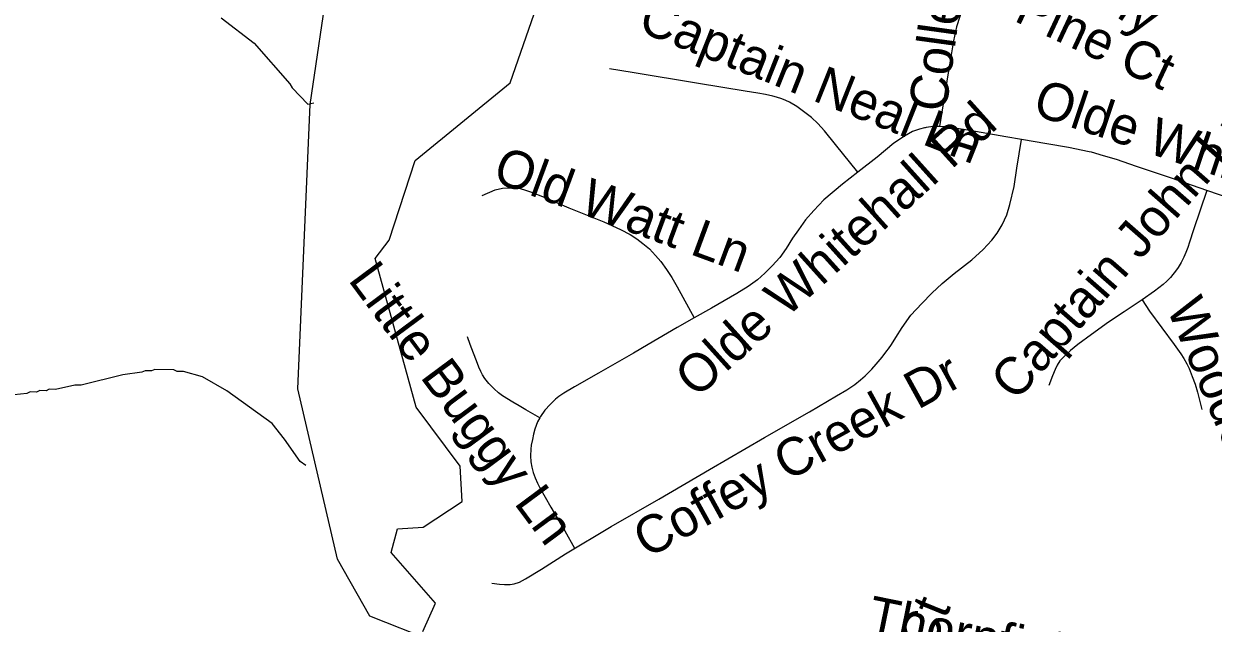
# Model space of a CAD drawing. Extents: x 1383679 to 1536984, y 460658 to 651027.
# Drawn here: x 1421601 to 1424590, y 516365 to 517873 of the extents above; entities that cross this region are included whole.
import ezdxf

# ---------------------------------------------------------------- set-up
doc = ezdxf.new("R2010")
doc.units = 0
for name, color, linetype in [('Default', 7, 'Continuous'), ('Exist Boundary Political City Limit New', 7, 'Continuous'), ('Exist Hydrographic Creek Single Shore', 7, 'Continuous'), ('Exist Hydrographic Misc Water Feature', 7, 'Continuous'), ('Exist Road Non-System Type 51', 7, 'Continuous'), ('Exist Road Non-System Type 51 Label', 7, 'Continuous'), ('Map Preparation Boundary City Limit Buffer Line', 7, 'Continuous')]:
    doc.layers.add(name, color=color, linetype=linetype)

msp = doc.modelspace()

# ---------------------------------------------------------------- linework, layer by layer
at = {"layer": 'Default'}
msp.add_lwpolyline([(1422603.5, 516344.2), (1422635.4, 516415.8), (1422524.4, 516543), (1422540.4, 516602.5), (1422604.6, 516606.3), (1422702.4, 516671.3), (1422697.2, 516759.8), (1422587.1, 516908.5), (1422484, 517282.3), (1422519.2, 517328.5), (1422584.4, 517528.7), (1422823.6, 517723.8), (1422904, 517956.5)], dxfattribs=at)
at = {"layer": 'Exist Boundary Political City Limit New'}
msp.add_lwpolyline([(1422603.5, 516344.2), (1422635.4, 516415.8), (1422524.4, 516543), (1422540.4, 516602.5), (1422604.6, 516606.3), (1422702.4, 516671.3), (1422697.2, 516759.8), (1422587.1, 516908.5), (1422484, 517282.3), (1422519.2, 517328.5), (1422584.4, 517528.7), (1422823.6, 517723.8), (1422904, 517956.5)], dxfattribs=at)
at = {"layer": 'Exist Hydrographic Creek Single Shore'}
msp.add_lwpolyline([(1424072.3, 513492.8), (1423994, 513542), (1423828.5, 513762.7), (1423689.5, 514339.8), (1423609.5, 514541.7), (1423406.5, 514821.5), (1423185.5, 515036), (1423056.5, 515229), (1423060.5, 515461.9), (1423124.5, 515746.2), (1423093.5, 515845.3), (1422831.5, 516093.5), (1422627.5, 516320.8), (1422470.6, 516383.1), (1422389.5, 516525.8), (1422289.5, 516954.5), (1422320.6, 517669.5), (1422416.5, 518317.5), (1422566.9, 518673)], dxfattribs=at)
at = {"layer": 'Exist Hydrographic Misc Water Feature'}
for points in [[(1422097.3, 517887.3), (1422179.9, 517823.5), (1422269.8, 517721.5), (1422275.6, 517711.5), (1422314.7, 517670.5), (1422329.7, 517674.1)], [(1422309.4, 516761.3), (1422295.2, 516771.4), (1422256.4, 516828.2), (1422225.3, 516866.9), (1422111, 516949.5), (1422049.7, 516984.8), (1422002.1, 516997.9), (1421986.1, 516998.2), (1421978.2, 517002.4), (1421930.2, 517003.5), (1421922.1, 516999.7), (1421906.1, 517000), (1421898, 516996.2), (1421849.8, 516989.3), (1421745.2, 516963.7), (1421729.2, 516964), (1421681, 516953.1), (1421665.1, 516953.5), (1421657, 516949.7), (1421641, 516950), (1421632.9, 516946.2), (1421616.9, 516946.6), (1421608.8, 516942.8), (1421576.7, 516939.5)]]:
    msp.add_lwpolyline(points, dxfattribs=at)
at = {"layer": 'Exist Road Non-System Type 51'}
for points in [[(1423965.7, 517924.5), (1423953.1, 517891.2), (1423944.4, 517865.2), (1423936.9, 517830), (1423925.6, 517759.1), (1423902.4, 517613.9)], [(1423696.5, 517499), (1423640.6, 517569.3), (1423613.4, 517602.9), (1423596.1, 517621.5), (1423580.2, 517636.5), (1423564, 517649.8), (1423543.6, 517664.1), (1423525, 517675.1), (1423515.5, 517679.8), (1423506.2, 517683.4), (1423492.6, 517687.7), (1423483.3, 517690.3), (1423464.4, 517694.4), (1423445.5, 517698.2), (1423413.4, 517703.2), (1423296.4, 517722.5), (1423129.6, 517750), (1423072.4, 517759.3)], [(1423902.4, 517613.9), (1423888.3, 517613.9), (1423886.2, 517613.9), (1423868.5, 517611.7), (1423865.9, 517611.1), (1423864.3, 517610.9), (1423852, 517607.4), (1423834.1, 517601.6), (1423814.4, 517590.3), (1423786.9, 517572.2), (1423745.3, 517537.5), (1423696.5, 517499)], [(1424107.7, 517581.9), (1424068.4, 517588.6), (1423978, 517603.8), (1423935.5, 517611.2), (1423932.1, 517611.7), (1423928, 517612.2), (1423902.9, 517613.9), (1423902.4, 517613.9)], [(1422777.5, 516466.1), (1422796.4, 516462.9), (1422809.3, 516462.2), (1422823, 516462.8), (1422833.6, 516464), (1422846.4, 516468.7), (1422861.6, 516476.4), (1422902.3, 516501.2), (1422962.2, 516539.4), (1423077, 516608.2), (1423196.9, 516677.1), (1423324.5, 516751.9), (1423462.3, 516831.8), (1423575.1, 516896.5), (1423642.9, 516936.8), (1423669.3, 516952.2), (1423689.5, 516965.8), (1423703.7, 516976.8), (1423715, 516987), (1423731.7, 517003.7), (1423743.2, 517016.4), (1423757.9, 517034), (1423770.1, 517050.1), (1423774, 517055.4), (1423781.6, 517066), (1423792.2, 517083.8), (1423808.3, 517109.1), (1423830.3, 517139.8), (1423857.4, 517169.5), (1423882.5, 517195.3), (1423908.7, 517219), (1423939.2, 517244.2), (1423983.3, 517279.2), (1424011.4, 517305.2), (1424033.5, 517328.3), (1424047, 517346.3), (1424059.1, 517366.8), (1424071, 517392.2), (1424079.1, 517418.4), (1424089.4, 517463.3), (1424096.5, 517509.8), (1424107.7, 517581.9)], [(1424574.1, 517453.3), (1424485.3, 517483.9), (1424397, 517514), (1424346.4, 517531.1), (1424314, 517540.8), (1424283.8, 517549.3), (1424278.1, 517550.8), (1424226.6, 517561.4), (1424171.8, 517570.9), (1424107.7, 517581.9)], [(1423696.5, 517499), (1423658.2, 517468.9), (1423611.8, 517429.4), (1423586.1, 517403.3), (1423565.5, 517379.8), (1423547.6, 517354.7), (1423532.9, 517333.1), (1423516.7, 517307.1), (1423500.9, 517285.1), (1423481.8, 517263.4), (1423463.5, 517245), (1423444.6, 517228.4), (1423421.6, 517211.6), (1423392.9, 517194.4), (1423329.1, 517157.6), (1423285.9, 517133)], [(1422752.9, 517440.5), (1422785.5, 517454.7), (1422804.2, 517459.1), (1422819.1, 517460.3), (1422835.7, 517459.9), (1422848.3, 517458.3), (1422861.5, 517454.3), (1422874.1, 517450.3), (1422908.5, 517436.3), (1422970.6, 517409.9), (1423058.2, 517374.4), (1423100.5, 517355.2), (1423124.5, 517342.4), (1423141.1, 517331.4), (1423156.2, 517320.1), (1423172.9, 517306.3), (1423188.6, 517290), (1423201.6, 517274.7), (1423215.9, 517254.5), (1423229.3, 517234.4), (1423243, 517210.8), (1423285.9, 517133)], [(1424574.1, 517453.3), (1424540.3, 517354.4), (1424530.1, 517323.3), (1424525.8, 517310), (1424521.1, 517297), (1424516.1, 517285.5), (1424509.1, 517272.1), (1424501.8, 517259.9), (1424495.3, 517250.2), (1424488.7, 517241.8), (1424482.5, 517234.7), (1424473.7, 517225.4), (1424464.4, 517217.1), (1424442.5, 517199.8), (1424411.6, 517178)], [(1424846.2, 517191.9), (1424834.8, 517234.2), (1424821.8, 517284.6), (1424812, 517309.9), (1424802.1, 517329.4), (1424791.9, 517345.6), (1424778.9, 517360.4), (1424766.4, 517373.7), (1424754.5, 517382.8), (1424740, 517392.2), (1424723.8, 517400.4), (1424680.1, 517417.2), (1424605.6, 517442.4), (1424574.1, 517453.3)], [(1424411.6, 517178), (1424366.3, 517148.3), (1424326.7, 517121.8), (1424283.8, 517090.8), (1424249.4, 517066), (1424249.3, 517065.9), (1424231.3, 517051), (1424211, 517031.7), (1424204.6, 517024.7), (1424197.8, 517013.9), (1424192.6, 517003.5), (1424186.1, 516986.9), (1424177.2, 516963.1)], [(1424411.6, 517178), (1424429.7, 517149.6), (1424491.4, 517066), (1424508.3, 517042.3), (1424515.8, 517030.5), (1424523.8, 517017), (1424529.5, 517005.3), (1424537.3, 516985.2), (1424544.2, 516966.6), (1424550, 516946.4), (1424561.3, 516902.5)], [(1423285.9, 517133), (1423242.9, 517108.5), (1423170.1, 517066), (1423132.8, 517044.2), (1423045.2, 516994), (1422984.9, 516959.7), (1422958, 516943.9), (1422945.2, 516935.1), (1422936.9, 516928.2), (1422923.5, 516915.5), (1422910.4, 516900.7), (1422899.6, 516885.1), (1422897.7, 516881.7)], [(1422897.7, 516881.7), (1422862.9, 516902), (1422845.5, 516911.4), (1422829.5, 516921), (1422803.6, 516936.9), (1422793.9, 516944.4), (1422782.7, 516954.9), (1422769.9, 516967.5), (1422759.8, 516980.3), (1422753.8, 516989.7), (1422749.5, 516998.1), (1422744.8, 517008.9), (1422738.4, 517024.7), (1422730.8, 517044.2), (1422722.9, 517066), (1422715.9, 517085.3)], [(1422897.7, 516881.7), (1422892, 516871.2), (1422885.3, 516852.7), (1422882, 516840.8), (1422878.9, 516827.3), (1422876.1, 516812.8), (1422875, 516802.9), (1422874.2, 516786.2), (1422875.3, 516771.2), (1422877.9, 516757.6), (1422881.3, 516743.8), (1422886, 516730.8), (1422892.2, 516717.4), (1422897, 516707.6), (1422925, 516656.6), (1422951.6, 516612.1), (1422960.3, 516597.4), (1422985.2, 516553.6)]]:
    msp.add_lwpolyline(points, dxfattribs=at)
at = {"layer": 'Map Preparation Boundary City Limit Buffer Line'}
msp.add_lwpolyline([(1422603.5, 516344.2), (1422635.4, 516415.8), (1422524.4, 516543), (1422540.4, 516602.5), (1422604.6, 516606.3), (1422702.4, 516671.3), (1422697.2, 516759.8), (1422587.1, 516908.5), (1422484, 517282.3), (1422519.2, 517328.5), (1422584.4, 517528.7), (1422823.6, 517723.8), (1422904, 517956.5)], dxfattribs=at)
msp.add_lwpolyline([(1422603.5, 516344.2), (1422635.4, 516415.8), (1422524.4, 516543), (1422540.4, 516602.5), (1422604.6, 516606.3), (1422702.4, 516671.3), (1422697.2, 516759.8), (1422587.1, 516908.5), (1422484, 517282.3), (1422519.2, 517328.5), (1422584.4, 517528.7), (1422823.6, 517723.8), (1422904, 517956.5)], dxfattribs=at)

# ---------------------------------------------------------------- texts
at = {"layer": 'Exist Road Non-System Type 51 Label'}
for s, rotation, p in [('Bushy', 326.3104, (1424126.9, 518036)), ('Colley', 82.1747, (1423918.1, 517647.9)), ('Pine Ct', 334.917, (1424086.2, 517880.9)), ('Captain Neal Ln', 338.2823, (1423140.3, 517855.8)), ('Olde Whitehall Rd', 341.4471, (1424132.3, 517645.7)), ('Olde Whitehall Rd', 41.98, (1423291.4, 516928.6)), ('Captain John Ln', 48.7963, (1424094.2, 516920.3)), ('Old Watt Ln', 339.7559, (1422775.2, 517477.5)), ('Little Buggy Ln', 306.6057, (1422414.1, 517228.5)), ('Wooden Peg Ct', 292.7142, (1424471.6, 517159.2)), ('Coffey Creek Dr', 28.8114, (1423167.2, 516526.8)), ('Wapiti Ct', 67.9009, (1423737.1, 515929.1)), ('Thornfield Rd', 348.4473, (1423716.5, 516341.6))]:
    msp.add_text(s, height=95, rotation=rotation, dxfattribs=at).set_placement(p)

doc.saveas('drawing.dxf')
